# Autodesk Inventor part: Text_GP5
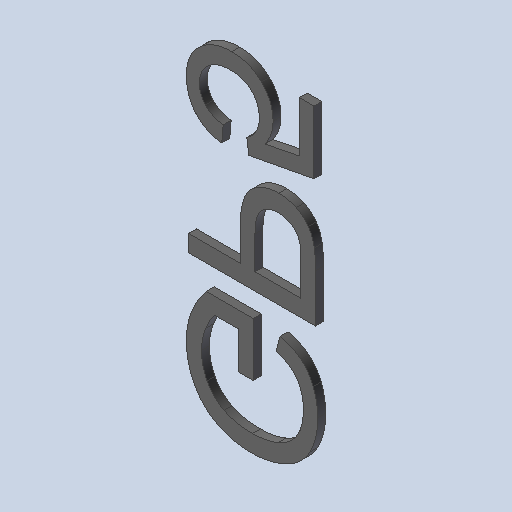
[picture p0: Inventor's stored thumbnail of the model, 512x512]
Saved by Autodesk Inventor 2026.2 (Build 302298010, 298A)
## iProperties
Created: 2026-10
Part Number: Text_GP5
Material: Générique
Document SubType Name: Modeling
Designer: mel
Density: 1 g/cm^3
Appearance: Par défaut
Author: mel
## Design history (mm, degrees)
feature "Base1"
feature "Base2"
feature "Base3"
node "Solide1"
node "Solide2"
node "Solide3"
